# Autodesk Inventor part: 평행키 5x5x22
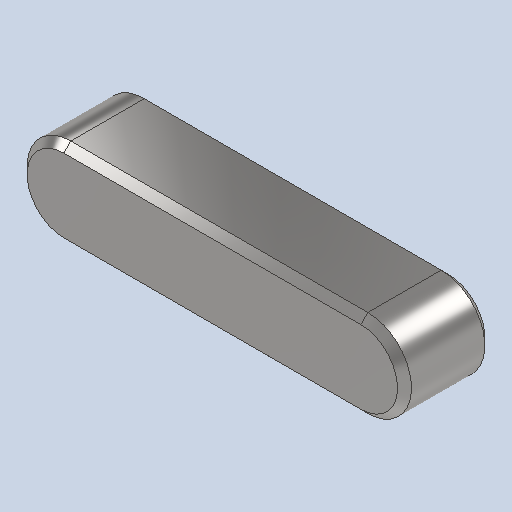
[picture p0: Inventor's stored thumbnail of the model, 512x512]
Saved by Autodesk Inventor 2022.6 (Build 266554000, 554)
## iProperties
Created: 2024-09
Part Number: 평행키 5x5x22
Material: 강철, 연강
Description: 키 및 해당 키홈
Document SubType Name: Modeling
Designer: Class 001
Density: 7.85 g/cm^3
Appearance: 기본값
Author: jhkim
Sending System: Autodesk Inventor 2025
Preprocessor: ST-DEVELOPER v20
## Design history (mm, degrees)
feature "Solid1"
node "솔리드1"
